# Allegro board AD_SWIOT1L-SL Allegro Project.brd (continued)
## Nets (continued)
AGND: C5.2(N2) C6.2(N2) C7.2(N2) C8.2(N2) C9.2(N2) C10.2(N2) C11.2(N2) C12.2(N2) C13.2(N2) C14.2(N2) C15.2(N2) C16.2(N2) C18.1 C19.1 C20.1 C21.2(N2) C22.2(N2) C23.2(N2) C24.2(N2) C25.1 C26.1 C27.1 C28.1 C29.1 C30.1 C31.1 C32.1 C33.2(N2) C34.2(N2) C35.2(N2) C36.2(N2) C37.2(N2) C38.2(N2) C39.2(N2) C40.2(N2) C41.2(N2) C42.1 C43.1 C44.1 C48.2(N2) C49.2(N2) C104.1 C105.1 C106.1 C110.1 C111.1 C112.1 C116.2(N2) C128.1 C129.1 C130.1 C136.1 C137.2(N2) C144.N(N2) C147.1 D1.2(N2) D2.2(N2) D3.2(N2) D4.2(N2) D17.1 P2.9(N9) P2.10 P4.1 P6.2 P6.4 P6.6 P6.8(N8) R28.2(N2) R47.2(N2) R50.2(N2) R51.2(N2) R52.2(N2) R53.2(N2) R54.2(N2) R56.2(N2) R70.2(N2) R76.2(N2) R78.2(N2) R80.2(N2) T1.8(SECDOT) TP1.1(N1) TP8.1(N1) TP10.1(N1) U2.8 U2.25 U2.28 U2.40 U2.41 U2.54 U2.PAD U3.1 U3.2 U3.14 U3.23 U3.30 U3.38 U3.47 U3.PAD U6.2 U6.10 U7.2 U7.10 U12.9 U12.10 U12.15 U12.16 U13.9 U13.10 U13.15 U13.16 U14.11 U14.12 U15.4 U15.9 U18.4 U25.4 U25.5 U25.16 U25.27 U25.PAD1
AVDD_H: C54.2(N2) C56.1 E1.2(N2) U8.16 U8.17
AVDD_L: C55.2(N2) C57.1 E2.2(N2) U8.22
AVSS: C20.2(N2) U2.27
DGND: C47.2(N2) C50.2(N2) C51.2(N2) C52.2(N2) C53.2(N2) C54.1 C55.1 C56.2(N2) C57.2(N2) C58.2(N2) C59.2(N2) C60.1 C61.1 C62.1 C63.1 C64.1 C65.1 C66.1 C67.1 C68.1 C69.1 C70.2(N2) C71.2(N2) C72.2(N2) C73.2(N2) C74.2(N2) C75.2(N2) C76.2(N2) C77.2(N2) C78.2(N2) C79.2(N2) C80.2(N2) C81.2(N2) C82.2(N2) C83.2(N2) C84.1 C85.2(N2) C86.2(N2) C87.2(N2) C88.1 C89.1 C90.1 C91.2(N2) C92.2(N2) C93.2(N2) C94.1 C95.1 C96.2(N2) C97.2(N2) C98.1 C99.2(N2) C100.2(N2) C101.2(N2) C102.2(N2) C103.2(N2) C107.2(N2) C108.1 C109.1 C115.N(N2) C117.2(N2) C118.2(N2) C119.1 C120.2(N2) C121.1 C122.2(N2) C123.2(N2) C124.2(N2) C125.2(N2) C126.2(N2) C127.2(N2) C131.1 C132.2(N2) C133.N(N2) C134.N(N2) C135.2(N2) C136.2(N2) C138.2(N2) C139.2(N2) C140.N(N2) C142.2(N2) C146.2(N2) D5.2(N2) D9.A(P) D19.2(N2) JP1.3 P1.3 P1.5 P1.9 Q12.1 Q12.3(S) Q13.2(S) Q20.2(S) Q21.2(S) R36.2(N2) R37.2(N2) R38.2(N2) R41.2(N2) R44.2(N2) R46.2(N2) R59.2(N2) R61.2(N2) R62.1 R126.2(N2) S1.2(B) T2.9 TP4.1(N1) TP6.1(N1) TP12.1(N1) TP14.1(N1) TP16.1(N1) U1.11 U1.27 U1.29 U1.47 U1.60 U1.80 U1.81 U1.85 U1.89(VSS_9) U1.98 U1.119 U1.136 U4.4 U4.5 U4.6 U4.7 U5.6 U5.PAD U6.11 U6.12 U7.11 U7.12 U8.PAD U9.B3 U9.C1 U9.E5(VSSQ_2) U10.B3 U10.C1 U10.E5(VSSQ_2) U11.4 U12.1 U12.2 U12.7 U12.8 U13.1 U13.2 U13.7 U13.8 U14.10 U16.2 U16.7 U16.10 U16.11 U16.PAD U17.3 U17.PAD U18.5 U19.5 U19.13 U25.3 U25.28 U25.33 U25.34 U25.PAD2 U25.PAD3 Y1.2 Y1.4
GND_EARTH: C113.2(N2) C143.2(N2) D6.3(E_3) P3.3(N3) R36.1 TP2.1(N1)
V5: C42.2(N2) U3.31
VCC_1: C131.2(N2) R64.1 U16.3
VDD_1: C34.1 Q6.1 Q6.2 Q6.3(S3) U3.17
VDD_2: C33.1 Q5.1 Q5.2 Q5.3(S3) U3.20
VDD_3: C35.1 Q7.1 Q7.2 Q7.3(S3) U3.41
VDD_4: C36.1 Q8.1 Q8.2 Q8.3(S3) U3.44
VDD_24V: C18.2(N2) C19.2(N2) C26.2(N2) C27.2(N2) R27.1 S2.6(NO2) U2.7 U2.42
VDD_24V_MAX14906: C32.2(N2) C41.1 C43.2(N2) Q5.5 Q5.6 Q5.7 Q5.8 Q6.5 Q6.6 Q6.7 Q6.8 Q7.5 Q7.6 Q7.7 Q7.8 Q8.5 Q8.6 Q8.7 Q8.8 R34.1 S2.5 U3.10(VLED_1) U3.11
VDDOK: DS9.C U3.3
VIN_SYS: C47.1 C138.1 C139.1 D11.A(P) D15.C D18.C JP1.1 R49.1 T1.1 U16.1(VIN) U25.30 U25.31
AD74413R_ADC_RDY: U1.75 U6.18
AD74413R_ADC_RDY_ISO: R84.2(N2) U2.52 U6.3
AD74413R_ALERT: U1.31 U25.38
AD74413R_ALERT_ISO: R79.2(N2) U2.53 U25.21
AD74413R_GPO_A: U1.45 U14.5
AD74413R_GPO_A_ISO: U2.19 U14.16
AD74413R_GPO_B: U1.46 U14.6
AD74413R_GPO_B_ISO: U2.20 U14.15
AD74413R_GPO_C: U1.48 U14.7
AD74413R_GPO_C_ISO: U2.21 U14.14
AD74413R_GPO_D: U1.49 U14.8
AD74413R_GPO_D_ISO: U2.22 U14.13
AD74413R_LDAC: U1.100 U25.37
AD74413R_LDAC_ISO: R78.1 U2.58 U25.22
AD74413R_RESET: U1.103 U25.36
AD74413R_RESET_ISO: R75.2(N2) U2.62 U25.23
ADIN1110_RESET: U1.121 U8.5
ADT75_OS__ALLERT: R94.2(N2) U1.39 U4.3
ALDO1V8: C22.1 C25.2(N2) U2.10
ALDO5V: C21.1 U2.9
CABLE+: C143.1 D6.1 L1.4(N4) P3.1 R73.1
CABLE-: C113.1 D6.2 L1.3 P3.2 R74.1
CASCODE_A: Q1.3 U2.64
CASCODE_B: Q2.3 U2.17
CASCODE_C: Q3.3 U2.32
CASCODE_D: Q4.3 U2.49
CCOMP_A: C1.1 U2.63
CCOMP_B: C4.1 U2.18
CCOMP_C: C2.1 U2.31
CCOMP_D: C3.1 U2.50
CH_1: C1.2(N2) C13.1 C40.1 D1.1 P6.1 R1.2(N2) R9.2(N2) R17.1 U3.15 U3.16
CH_2: C4.2(N2) C14.1 C39.1 D2.1 P6.3 R3.2(N2) R11.2(N2) R18.1 U3.21 U3.22
CH_3: C2.2(N2) C15.1 C38.1 D3.1 P6.5 R5.2(N2) R13.2(N2) R19.1 U3.39 U3.40
CH_4: C3.2(N2) C16.1 C37.1 D4.1 P6.7 R7.2(N2) R15.2(N2) R20.1 U3.45 U3.46
DATA_AND_POWER_N: C46.2(N2) L1.2 L2.2 R71.2(N2) R74.2(N2)
DATA_AND_POWER_P: C45.2(N2) L1.1 L2.3 R72.2(N2) R73.2(N2)
DATA_N: C46.1 D19.1 R23.2(N2) R24.2(N2) R71.1
DATA_P: C45.1 D5.1 R22.2(N2) R25.2(N2) R72.1
DLDO1V8: C23.1 C130.2(N2) U2.57
DLDO_1P1: C58.1 C60.2(N2) U8.23 U8.24
FIELD_POWER_DETECTED: U1.90 U18.6
FIELD_POWER_DETECTED_ISO: S2.2 U18.3
FLED: DS2.C DS4.C DS6.C DS8.C U3.4
G1: Q6.4 U3.18
G2: Q5.4 U3.19
G3: Q7.4 U3.42
G4: Q8.4 U3.43
GATE: Q9.4 R40.2(N2) U19.12
HYP_CLK: U1.65 U9.B2 U10.B2
HYP_CLKN: U1.64 U9.B1 U10.B1
HYP_CS0N: U1.52 U10.A3
HYP_CS1N: R82.2(N2) U1.44 U9.A3
HYP_D0: U1.53 U9.D3 U10.D3
HYP_D1: U1.58 U9.D2 U10.D2
HYP_D2: U1.62 U9.C4 U10.C4
HYP_D3: U1.66 U9.D4 U10.D4
HYP_D4: U1.56 U9.D5 U10.D5
HYP_D5: U1.59 U9.E3 U10.E3
HYP_D6: U1.63 U9.E2 U10.E2
HYP_D7: U1.67 U9.E1 U10.E1
HYP_RESET: U1.50 U9.A4 U10.A4
HYP_RWDS: U1.68 U9.C3 U10.C3
I2C1_SCL: R95.2(N2) U1.20 U4.2
I2C1_SDA: R96.2(N2) U1.19 U4.1
INT: U1.127 U8.25
L1: R33.2(N2) U3.8
L2: R32.2(N2) U3.7
L3: R31.2(N2) U3.6
L4: R30.2(N2) U3.5
LED1: Q20.1 U1.144
LED2: Q21.1 U1.143
LGATE1: Q12.2 U19.9
LGATE2: Q12.4 U19.8
LINK_ST: U1.130 U8.4
LTC9111_IN: C118.1 D7.C D8.C D9.C Q9.5 Q9.6 Q9.7 Q9.8 R42.1 U19.3
LX: L4.1 U16.12
MAX14906_D1: R129.2(N2) U1.97 U12.6
MAX14906_D1_ISO: R50.1 R132.2(N2) U3.13 U12.11
MAX14906_D2: R127.2(N2) U1.96 U12.5
MAX14906_D2_ISO: R52.1 R134.2(N2) U3.24 U12.12
MAX14906_D3: R130.2(N2) U1.95 U13.6
MAX14906_D3_ISO: R51.1 R133.2(N2) U3.37 U13.11
MAX14906_D4: R128.2(N2) U1.94 U13.5
MAX14906_D4_ISO: R53.1 R135.2(N2) U3.48 U13.12
MAX14906_EN: U1.72 U7.15
MAX14906_EN_ISO: U3.27 U7.6
MAX14906_FAULT: U1.71 U7.17
MAX14906_FAULT_ISO: R69.2(N2) U3.29 U7.4
MAX14906_READY: U1.70 U7.18
MAX14906_READY_ISO: R70.1 U3.26 U7.3
MAX14906_SYNCH: R37.1 U1.91 U7.16
MAX14906_SYNCH_ISO: U3.36 U7.5
MAXQ1065_PDWN: U1.3 U5.7
MAXQ1065_RDY: U1.1 U5.11
MAXQ1065_WDI: U1.2 U5.9(WDI)
PMOD_IRQ: U1.93 U18.7
PMOD_IRQ_ISO: P2.1 U18.2
POWER_N: C114.2(N2) D7.A(P) L2.4(N4) Q11.3 Q12.5 Q12.6 U19.2
POWER_P: D8.A(P) L2.1 Q10.3 Q12.7 Q12.8 R39.1 U19.1
PWRGD: Q13.1 R57.2(N2) U25.35
REFOUT: C106.2(N2) U2.29 U2.30
RSTN: C180.2(N2) P1.10(N5) R106.2(N2) R125.2(N2) S1.1 U1.114
RXN: R21.1 R23.1 U8.13
RXP: R25.1 R26.1 U8.14
SCCP: Q10.1 Q11.1 U19.7
SENSEH_A: R2.1 U2.1
SENSEH_B: R4.1 U2.16
SENSEH_C: R6.1 U2.33
SENSEH_D: R8.1 U2.48
SENSEHF_A: C6.1 R10.1 U2.2
SENSEHF_B: C8.1 R12.1 U2.15
SENSEHF_C: C10.1 R14.1 U2.34
SENSEHF_D: C12.1 R16.1 U2.47
SENSEL_A: R1.1 U2.3
SENSEL_B: R3.1 U2.14
SENSEL_C: R5.1 U2.35
SENSEL_D: R7.1 U2.46
SENSELF_A: C5.1 R9.1 U2.4
SENSELF_B: C7.1 R11.1 U2.13
SENSELF_C: C9.1 R13.1 U2.36
SENSELF_D: C11.1 R15.1 U2.45
SLED: DS1.C DS3.C DS5.C DS7.C U3.9
SLEW: JP1.2(COM) U25.32
SPI0_MISO: U1.138 U5.4
SPI0_MOSI: U1.141 U5.3
SPI0_SCK: U1.142 U5.2
SPI0_SS0: U1.10 U5.5
SPI1_MISO: U1.117 U6.17
SPI1_MISO_ISO: P2.6 U3.32 U6.4
SPI1_MOSI: U1.118 U6.15
SPI1_MOSI_ISO: P2.4 U3.35 U6.6
SPI1_SCK: U1.115 U6.14
SPI1_SCK_ISO: P2.8 U3.33 U6.7
SPI1_SS2: U1.92 U7.13
SPI1_SS2_ISO: P2.2 U7.8
SPI1_SS3: U1.116 U6.13
SPI1_SS3_ISO: U3.34 U6.8
SPI2_MISO__SPI_CFG1: U1.123 U8.2
SPI2_MOSI: U1.124 U8.1
SPI2_SCK: U1.122 U8.38
SPI2_SS0: U1.125 U8.29
SPI3_MISO: U1.35 U25.1
SPI3_MISO_ISO: R80.1 U2.51 U25.7
SPI3_MOSI: U1.36 U25.41
SPI3_MOSI_ISO: R76.1 U2.60 U25.8
SPI3_SCK: U1.30 U25.40
SPI3_SCK_ISO: R77.2(N2) U2.59 U25.9
SPI3_SS3: U1.32 U25.2
SPI3_SS3_ISO: U2.61 U25.6
SPI_CFG1: U1.120 U8.37
SPIXF_SCK: U1.13 U11.6
SPIXF_SDIO0: U1.17 U11.5
SPIXF_SDIO1: U1.15 U11.2
SPIXF_SDIO2: U1.22 U11.3(WP_N/SIO2)
SPIXF_SDIO3: U1.23 U11.7
SPIXF_SS0: U1.12 U11.1
SPOE_OUT: D15.A(P) R123.2(N2)
SPOE_OUT_O: C120.1 C122.1 Q9.1 Q9.2 Q9.3(S3) R66.1 R123.1 TP3.1(N1) U19.11
STBY: C135.1 U19.4(STBY) U19.10
SW: D14.A(P) R55.2(N2) R68.2(N2) T2.3 U15.5
SWP: D12.A(P) T1.4 U25.29
SWPD_EN: U1.133 U8.33
TC: R67.2(N2) U15.8
TCK: P1.4 U1.110
TMS: P1.2 U1.113
TS_CAPT: U1.129 U8.40
TS_TIMER__MS_SEL: U1.131 U8.30
TX2P4_EN: U1.134 U8.31
TXN: R24.1 R26.2(N2) U8.12
TXP: R21.2(N2) R22.1 U8.15
UART0_RX: P1.8 U1.132
UART0_TX: P1.6 U1.137
UNNAMED_2_ADMAXQ1065_I121_CEXT: C100.1 U5.1
UNNAMED_2_ADMAXQ1065_I121_RESETOUT: R106.1 U5.10
UNNAMED_2_CAP_I138_N1: C180.1 R126.1
UNNAMED_2_DIOLED_I129_N: DS17.C Q20.3
UNNAMED_2_DIOLED_I129_P: DS17.A(P) R116.2(N2)
UNNAMED_2_DIOLED_I131_N: DS18.C Q21.3
UNNAMED_2_DIOLED_I131_P: DS18.A(P) R117.2(N2)
UNNAMED_6_ADIN1110V2_I1_CEXT2: C52.1 U8.19
UNNAMED_6_ADIN1110V2_I1_CEXT3: C53.1 U8.20
UNNAMED_6_ADIN1110V2_I1_LED0: R102.2(N2) U8.3
UNNAMED_6_ADIN1110V2_I1_LED1: R104.2(N2) R105.2(N2) U8.6
UNNAMED_6_ADIN1110V2_I1_TEST1: R35.1 U8.26
UNNAMED_6_CAP_I79_N2: C119.2(N2) R40.1
UNNAMED_6_CAP_I114_N1: C114.1 R39.2(N2)
UNNAMED_6_CAP_I146_N1: C117.1 R42.2(N2)
UNNAMED_6_CAPP_I143_N1: C115.P C133.P R66.2(N2)
UNNAMED_6_DIOLED_I64_N: DS10.C R102.1
UNNAMED_6_DIOLED_I147_N: DS11.C R105.1
UNNAMED_6_RES_I107_N1: Q11.2(S) R41.1
UNNAMED_6_RES_I109_N1: Q10.2(S) R38.1
UNNAMED_7_ADLT8304_I142_EN: R28.1 R29.1 U15.1
UNNAMED_7_ADLT8304_I142_RFB: R55.1 U15.6
UNNAMED_7_ADLT8304_I142_RREF: R54.1 R67.1 U15.7
UNNAMED_7_ADMAX17761_I143_EN: R49.2(N2) R59.1 U16.4
UNNAMED_7_ADMAX17761_I143_FB: R60.2(N2) R61.1 R63.1 U16.8
UNNAMED_7_ADMAX17761_I143_RESETN: R64.2(N2) U16.5
UNNAMED_7_ADMAX17761_I143_RT: R62.2(N2) U16.6
UNNAMED_7_ADMAX17761_I143_SS: C127.1 U16.9
UNNAMED_7_ADP22X_I83_ADJ1: R43.2(N2) R44.1 U17.8
UNNAMED_7_ADP22X_I83_ADJ2: R45.2(N2) R46.1 U17.4
UNNAMED_7_ADP1032_I2_SW2: L3.1 U25.17
UNNAMED_7_ADP1032_I2_SYNC: R56.1 U25.14
UNNAMED_7_CAP_I60_N1: C126.1 R63.2(N2)
UNNAMED_7_CAP_I103_N1: C137.1 U15.2
UNNAMED_7_CAP_I154_N2: C141.2(N2) R68.1
UNNAMED_7_CAP_I167_N1: C145.1 R83.2(N2)
UNNAMED_7_DIO_I14_P: D10.A(P) T1.5
UNNAMED_7_DIOLED_I159_N: DS12.C Q13.3
UNNAMED_7_DIOLED_I159_P: DS12.A(P) R81.2(N2)
UNNAMED_7_DIOSCHOTTKY_I9_N: D11.C D12.C
UNNAMED_7_DIOSCHOTTKY_I132_P: D16.A(P) R83.1 T2.7
UNNAMED_7_DIOSCHOTTKY_I135_N: D13.C D14.C
UNNAMED_7_RES_I152_N1: R47.1 S2.3
UNNAMED_7_RES_I153_N1: R58.1 S2.1
UNNAMED_8_DIOLED_I6_P: DS9.A(P) R34.2(N2)
UNNAMED_8_DIOLED_I35_P: DS7.A(P) DS8.A(P) R33.1
UNNAMED_8_DIOLED_I37_P: DS5.A(P) DS6.A(P) R32.1
UNNAMED_8_DIOLED_I39_P: DS3.A(P) DS4.A(P) R31.1
UNNAMED_8_DIOLED_I41_P: DS1.A(P) DS2.A(P) R30.1
UNNAMED_9_AD74413_I30_CPUMPN: C17.2(N2) U2.26
UNNAMED_9_AD74413_I30_CPUMPP: C17.1 U2.24
UNNAMED_9_DIOBAV99LT1_I116_C: CR1.3 R2.2(N2) R10.2(N2) R17.2(N2)
UNNAMED_9_DIOBAV99LT1_I116_P: CR1.1(P) Q1.1 Q1.2 Q1.5 Q1.6
UNNAMED_9_DIOBAV99LT1_I117_C: CR2.3 R4.2(N2) R12.2(N2) R18.2(N2)
UNNAMED_9_DIOBAV99LT1_I117_P: CR2.1(P) Q2.1 Q2.2 Q2.5 Q2.6
UNNAMED_9_DIOBAV99LT1_I118_C: CR3.3 R6.2(N2) R14.2(N2) R19.2(N2)
UNNAMED_9_DIOBAV99LT1_I118_P: CR3.1(P) Q3.1 Q3.2 Q3.5 Q3.6
UNNAMED_9_DIOBAV99LT1_I119_C: CR4.3 R8.2(N2) R16.2(N2) R20.2(N2)
UNNAMED_9_DIOBAV99LT1_I119_P: CR4.1(P) Q4.1 Q4.2 Q4.5 Q4.6
VIOUTN_A: CR1.2 U2.6
VIOUTN_B: CR2.2 U2.11
VIOUTN_C: CR3.2 U2.38
VIOUTN_D: CR4.2 U2.43
VIOUTP_A: Q1.4(S) U2.5
VIOUTP_B: Q2.4(S) U2.12
VIOUTP_C: Q3.4(S) U2.37
VIOUTP_D: Q4.4(S) U2.44(VIOUTP_D)
VOUT1: C24.1 C48.1 D10.C R27.2(N2) TP7.1(N1) U25.18
VOUT2: C49.1 L3.2(N2) R48.2(N2) TP9.1(N1) U25.15(VOUT2)
XTAL_I: C50.1 U8.8 Y1.1
XTAL_O: C51.1 U8.9(XTAL_O) Y1.3(N2)

Pads without a net: P1 7; P2 3 5 7; T1 2 3 6 7; T2 1 2 4 6 8 10; U1 4 6 7 8 16 24 25 26 28 34 37 38 40 41 42 43 51 57 61 69 73 74 77 78 79 82 83 84 86 87 101 102 104 105 106 107 108 109 112 135 139 140; U2 39; U3 28; U5 8; U6 5 9 16 19; U7 7 9 14 19; U8 7 10 11 18 21 27 28 32 34 36 39; U9 A2 A5 B5 C2 C5; U10 A2 A5 B5 C2 C5; U12 4 13; U13 4 13; U14 2 3 4 9 17 18 19; U19 6; U25 11 12 13 19 24 25 26

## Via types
v1: diameter 0.508, hole 0.254, TOP to BOTTOM, 1639 vias
v2: diameter 0.457, hole 0.254, TOP to BOTTOM, 51 vias

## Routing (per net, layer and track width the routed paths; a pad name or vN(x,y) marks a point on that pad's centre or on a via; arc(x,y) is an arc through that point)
1V1: length 60.9
  TOP w0.254: 47.45,102.83 U1.5 ; U1.88 39.45,79.18 ; 42.95,102.83 U1.14
  TOP w0.457: v1(43.83,103.22) 43.37,103.68 C78.1 42.95,102.83 ; v1(48.19,103.68) C79.1 47.45,102.83
  TOP w0.483: 39.45,79.18 v1(39.45,78.6)
  TOP w0.508: 57.97,105.01 61.53,105.01 TP15.1 ; v1(39.45,78.6) 38.9,78.6 38.87,78.57 C80.1
  BOTTOM w0.508: v1(39.45,78.6) 39.45,79.88
  BOTTOM w0.635: v1(48.19,103.68) 50.12,103.68 50.93,102.87 50.93,102.87 52.62,101.18 56.12,101.18 56.76,101.81 56.76,104.35 v1(57.24,104.83) v1(57.97,104.83) v1(58.68,104.83) ; v1(48.19,103.68) 48.19,102.67 40.91,95.39 40.91,81.34 39.45,79.88 ; v1(48.19,103.68) 44.29,103.68 v1(43.83,103.22)
1V8: length 105.5
  TOP w0.254: U1.126 52.47,90.69 ; U9.B4 7.85,91.1 7.85,92.02 9,93.17 R82.1 ; U1.111 52.47,83.19 ; U1.33 33.45,102.7 ; U10.D1 16.18,88.04 16.17,88.04 ; C68.2 28.17,90.69 U1.55 ; U9.D1 4.76,88.04 ; U1.21 39.45,102.68 ; 44.95,78.98 U1.99
  TOP w0.288: U10.E4 19.26,88.12 19.26,90.12 U10.B4 ; U9.B4 7.84,90.12 7.84,88.12 U9.E4
  TOP w0.483: v1(38.65,102.9) C62.2 C66.2 39.45,102.68 ; 4.76,88.04 C91.1 ; C89.2 20.96,86.42 U10.E4 ; 44.95,78.98 45.15,78.78 C82.1 C83.1 v1(45.15,76.82) ; U11.8 C96.1 29.23,103.84 v1(30.18,102.89) ; C85.1 16.17,88.04 ; 33.45,102.7 C67.2 C63.2 v1(32.65,102.89) ; v1(73.01,104.76) C101.1 P1.1 ; v1(52.75,89.89) C65.2 C69.2 52.47,90.69 ; v1(52.77,82.18) 53.18,82.59 C142.1 52.47,83.19 ; U9.E4 9.54,86.42 C94.2 ; C68.2 C64.2 26.47,90.37 v1(26.3,90.2)
  TOP w0.635: v1(22.6,80.68) C87.1 C88.2 C89.2 ; v1(5.81,81.85) 3.51,84.14 C90.2 C92.1 C91.1 ; C85.1 C86.1 C84.2 v1(14.92,81.14) ; v1(11.17,81.14) C93.1 C95.2 C94.2
  L2_PWR w0.457: TP13.1 9.51,81.43 ; TP13.1 10.44,80.5 ; TP13.1 8.59,80.5 ; TP13.1 9.51,79.57
  L2_PWR w0.508: v1(26.3,90.2) 27.4,91.3 27.4,99.09
  BOTTOM w0.254: v1(73.01,104.76) 69.48,101.23 61.31,101.23 59.79,99.71 v1(58.13,99.71)
  vias: v1(57.42,100.42) v1(57.42,99.71) v1(58.13,100.42)
3V3: length 69.7
  TOP w0.178: 57.32,87.6 U8.35 ; 45.45,102.7 U1.9
  TOP w0.254: U1.54 28.17,91.19 C70.1 ; U1.18 40.95,102.7 ; U1.128 52.47,91.69 ; U1.76 33.45,79.18
  TOP w0.279: 63.88,99.67 U5.12 ; U17.1 U17.2 v1(53.51,102.74)
  TOP w0.305: U25.39 57.73,59.92 57.39,60.26 ; U4.8 C97.1
  TOP w0.33: U7.20 16.1,75.83 ; U6.20 8.14,75.83 ; 51.25,75.83 U14.1
  TOP w0.457: 57.39,60.26 57.23,60.42 C121.2 56.9,61.26 56.4,61.76 v1(56.4,62.14)
  TOP w0.483: 8.14,75.83 C102.1 v1(8.14,77.07) ; R104.1 DS11.A v1(62.66,79.26) ; C70.1 C75.1 26.54,91.51 26.34,91.71 v1(26.32,91.71) ; 57.32,87.6 C59.1 C61.2 v1(56.2,89.14) ; R127.1 v1(40.21,75.93) C108.2 U12.3 ; v1(63.88,102.21) C98.2 C99.1 63.88,99.67 ; v1(41.75,102.97) C76.1 C72.1 40.95,102.7 ; v1(16.1,77.07) C103.1 16.1,75.83 ; R128.1 v1(29.54,75.93) C109.2 U13.3 ; E1.1 v1(69.66,88.78) ; R117.1 v1(74.24,99.37) ; E2.1 v1(64.61,93.48) ; R116.1 74.87,104.38 v1(74.23,104.38) ; 45.45,102.7 C73.1 C77.1 46.24,103.67 v1(46.24,102.9) ; v1(51.25,77.32) C107.1 51.25,75.83 ; R130.1 v1(24.83,75.93) ; R35.2 v1(59.2,92.8) ; 52.47,91.69 C71.1 C74.1 v1(52.75,92.49) ; v1(8.63,100.26) C97.1 ; C81.1 v1(33.45,78.65) 33.45,79.18 ; R125.1 v1(54.08,85.42) ; v1(17.31,103.44) R94.1 R95.1 R96.1 ; R57.1 v1(60.19,63.74) ; R129.1 v1(35.51,75.93) ; v1(58.2,78.93) DS10.A ; v1(61.2,66.1) R81.1
  TOP w0.508: U18.8 C146.1 v1(2.99,75.4)
  L2_PWR w0.508: v1(26.32,91.71) 26.32,99.11
  vias: v1(57.98,102.24) v1(58.31,74.64) v1(58.31,73.93) v1(58.31,73.22) v1(59.01,74.64) v1(59.01,73.93) v1(59.01,73.22) v1(60.47,102.75) v1(60.47,102.05) v1(61.18,102.75) v1(61.18,102.05)
3V3_ISO: length 112.4
  TOP w0.254: U25.10 57.73,50.66 57.62,50.55 ; U6.1 C104.2 ; U7.1 C105.2
  TOP w0.279: v1(32.09,51.64) 31.81,51.64 31.33,52.12 U3.12
  TOP w0.305: 29.75,40.69 29.37,40.31 U2.23 ; U2.55 27.87,29.52 28.11,29.27 28.37,29.52 U2.56 ; 31.63,60.4 31.33,60.1 U3.25 ; U25.20 62.73,50.96
  TOP w0.33: U14.20 51.25,66.51
  TOP w0.457: 62.73,50.96 63.74,49.95 C128.2 v1(63.74,49.18) ; R79.1 v1(55.9,42.86) ; v1(53.98,47.41) R75.1 53.98,48.97 R77.1 ; v1(56.73,49.44) C129.2 57.25,50.18 57.62,50.55 ; R58.2 v1(54.75,30.88)
  TOP w0.483: 29.75,40.69 29.94,40.88 C29.2 29.94,42.52 29.46,43.01 C28.2
  TOP w0.508: 31.63,60.4 31.73,60.51 C44.2 v1(31.73,61.95) v1(31.73,62.69) ; v1(30.24,65.65) C111.2 U13.14 ; v1(51.25,65) C112.2 51.25,66.51 ; v1(2.99,66.92) C147.2 U18.1 ; v1(28.11,25.69) C31.2 C30.2 28.11,29.27 ; R132.1 v1(35.5,65.25) ; R134.1 v1(39.97,65.25) ; R135.1 v1(29.3,65.25) ; C105.2 v1(16.1,65.25) ; v1(40.91,65.65) C110.2 U12.14 ; v1(8.14,65.25) C104.2 8.91,65.99 R84.1 ; v1(19.45,64.25) R69.1 ; R133.1 v1(24.83,65.25)
  L2_PWR w0.457: 6.91,49.71 P2.11 ; P2.11 8.02,50.83 ; P2.11 9.14,49.71 ; P2.11 8.02,48.6 ; P2.12 6.6,49.71 ; P2.12 5.48,50.83 ; P2.12 4.37,49.71 ; P2.12 5.48,48.6
  BOTTOM w0.457: v1(55.9,42.86) 55.9,41.83 54.75,40.67 v1(54.75,30.88)
  BOTTOM w0.508: 32.08,51.64 31.49,51.64 31.49,51.65 ; 32.08,51.64 v1(32.09,51.64) 31.49,51.04 ; 32.08,51.64 31.49,52.23
  BOTTOM w0.762: v1(31.73,62.69) v1(31.73,61.95) 31.49,61.71 31.49,45.73 v1(29.58,43.82) ; 28.67,43.82 29.58,42.91 ; 28.67,43.82 v1(28.66,43.82) ; 28.67,43.82 v1(29.58,43.82) ; 29.58,42.91 v1(29.58,43.82) ; 29.58,42.91 29.58,41.49 32.96,38.11 32.96,31.38 28.11,26.53 v1(28.11,25.69)
  vias: v1(61.11,43.75) v1(61.11,43.04) v1(61.82,43.75) v1(61.82,43.04)
3V3_O: length 12.4
  TOP w0.457: 58.18,68.42 TP11.1 ; TP11.1 58.18,70.28 ; TP11.1 57.25,69.35 ; TP11.1 59.11,69.35
  TOP w0.508: v1(63.64,78.28) R60.1
  L2_PWR w0.508: v1(65.27,70.98) 65.27,76.66 v1(63.64,78.28)
24V_EXT: length 36.4
  TOP w0.457: R29.2 59.4,13.48 ; R29.2 60.13,12.88 ; R29.2 58.66,12.88
  TOP w0.762: S2.4 61.94,29.98 ; S2.4 63.39,31.43 ; S2.4 63.39,28.54 ; S2.4 64.84,29.98 ; C144.P 59.65,24.22 ; C144.P 63.38,24.22 ; C144.P 61.51,25.31 ; C144.P 61.51,23.12 ; D17.2 50,20.19 ; D17.2 52.8,20.19 ; D17.2 51.4,21.73 ; D17.2 51.4,18.65 ; P4.2 56.54,13.49 ; P4.2 53.79,13.49 ; P4.2 55.16,12.12 ; P4.2 55.16,14.87
  L2_PWR w0.762: P4.2 55.16,14.87 ; P4.2 55.16,12.12 ; P4.2 56.54,13.49 ; P4.2 53.79,13.49
  L2_PWR w0.889: S2.4 64.82,29.98 ; S2.4 63.39,28.55 ; S2.4 63.39,31.42 ; S2.4 61.95,29.98
  vias: v1(54.65,20.41) v1(54.65,19.14) v1(54.65,17.87) v1(54.65,16.6) v1(55.92,20.41) v1(55.92,19.14) v1(55.92,17.87) v1(55.92,16.6) v1(57.19,20.41) v1(57.19,19.14) v1(57.19,17.87) v1(57.19,16.6) v1(63.87,6.06) v1(63.87,5.35) v1(64.59,6.06) v1(64.59,5.35) v1(65.6,29.98) v1(65.6,28.71) v1(65.6,27.44) v1(65.6,26.17) v1(65.6,24.9) v1(66.87,29.98) v1(66.87,28.71) v1(66.87,27.44) v1(66.87,26.17) v1(66.87,24.9) v1(68.14,29.98) v1(68.14,28.71) v1(68.14,27.44) v1(68.14,26.17) v1(68.14,24.9) v1(69.41,29.98) v1(69.41,28.71) v1(69.41,27.44) v1(69.41,26.17) v1(69.41,24.9)
36V: length 3.7
  TOP w0.508: TP5.1 89.74,26.94 ; TP5.1 88.81,27.87 ; TP5.1 87.89,26.94 ; TP5.1 88.81,26.01
AGND: length 194.8
  TOP w0.254: U14.12 v1(46.05,66.31) ; U14.11 v1(45.4,66.02) ; U7.10 v1(21.95,66.31) ; U6.10 v1(13.99,66.31)
  TOP w0.457: U7.2 16.75,68.84 ; C20.1 v1(26.74,44.88) ; C20.1 v1(26.74,46.73) ; C20.1 v1(25.43,45.81) ; C20.1 27.88,45.81 ; C137.2 R28.2 ; C137.2 60.16,7.55 ; C137.2 58.63,7.55 ; C137.2 59.4,6.41 ; 18.92,36.69 C9.2 19.45,36.12 ; 64.64,49.34 C128.1 ; C128.1 64.64,50.48 ; C128.1 65.18,49.91 ; 26.09,42.06 C106.1 v1(26.09,40.73) ; 55.83,49.61 C129.1 55.3,50.18 ; 70.58,37.87 TP8.1 ; TP8.1 69.65,38.79 ; TP8.1 70.58,39.72 ; TP8.1 71.5,38.79 ; C5.2 38.31,32.24 ; P2.10 5.48,53.37 ; P2.10 4.37,52.25 ; P2.10 5.48,51.14 ; P2.10 6.6,52.25 ; 50.35,66.31 C112.1 49.81,65.73 ; 52.44,50.26 R76.2 52.44,51.41 ; 18.92,32.47 C11.2 ; 6.06,69.78 U18.4 6.67,68.57 ; C42.1 30.38,63.34 ; C42.1 29.52,64.36 ; C42.1 29.52,62.33 ; 52.44,52.17 R80.2 52.44,53.31 ; C8.2 38.31,38.88 ; 39.39,34.36 C25.1 39.96,34.89 ; 36.98,34.31 C21.2 38.13,34.31 ; P2.9 8.02,53.37 ; P2.9 9.14,52.25 ; P2.9 8.02,51.14 ; P2.9 6.91,52.25 ; 20.25,34.32 TP1.1 ; TP1.1 21.99,35.06 ; TP1.1 21.74,34.32 ; TP1.1 20.25,35.81 ; 59.49,41.42 R47.2 ; R47.2 60.02,42 ; R47.2 59.49,42.57 ; R28.2 59.97,9.23 ; R28.2 58.83,9.23 ; 52.43,44.61 TP10.1 ; TP10.1 54.28,44.61 ; TP10.1 53.36,43.68 ; TP10.1 53.36,45.54 ; 53.57,46.27 R78.2 54.1,45.7 ; 33.17,61.22 C44.1 32.63,60.65 ; 18.92,30.06 C12.2 ; 61.67,18.56 R54.2 61.13,17.99 ; 1.68,66.02 C147.1 2.25,65.49 ; 22.18,34.72 C27.1 23.32,34.72 ; C6.2 38.31,29.83 ; 58.39,50.36 R56.2 ; 38.55,34.36 C22.2 ; U6.2 8.79,68.84 ; C19.1 38.31,33.54 ; 18.92,39.11 C10.2 ; C7.2 38.31,36.47
  TOP w0.483: C41.2 v1(32.78,50.9) ; C29.1 30.84,42.44
  TOP w0.508: U13.10 v1(25.16,67.2) ; C110.1 v1(41.81,65.65) ; C23.2 C130.1 v1(29.77,25.69) ; C147.1 v1(2.99,66.02) ; R50.2 v1(35.5,66.39) ; R52.2 v1(39.97,66.39) ; U13.9 v1(23.89,67.2) ; C105.1 v1(15.2,65.25) ; U12.10 v1(35.83,67.2) ; U18.4 v1(6.06,67.2) ; R53.2 v1(29.3,66.39) ; R70.2 v1(17.74,64.25) ; C112.1 v1(50.35,65) ; C104.1 v1(7.24,65.25) ; 27.4,27.97 27.21,27.79 C30.1 C31.1 v1(27.21,25.69) ; U12.15 v1(42.18,67.2) ; C111.1 v1(31.14,65.65) ; U13.15 v1(31.51,67.2) ; U12.16 v1(43.45,67.2) ; C44.1 v1(32.63,61.95) ; R51.2 v1(24.83,66.39) ; U12.9 v1(34.56,67.2) ; U13.16 v1(32.78,67.2)
  TOP w0.635: P6.8 15.28,8.11 ; P6.8 16.53,6.87 ; P6.8 15.28,5.62 ; P6.8 14.04,6.87 ; P6.2 39.39,6.87 ; P6.2 38.14,8.11 ; P6.2 38.14,5.62 ; P6.2 36.9,6.87 ; 21.66,6.87 P6.6 ; P6.6 22.9,5.62 ; P6.6 24.15,6.87 ; P6.6 22.9,8.11 ; 29.28,6.87 P6.4 ; P6.4 30.52,5.62 ; P6.4 31.77,6.87 ; P6.4 30.52,8.11
  TOP w0.762: 48.79,13.49 P4.1 ; P4.1 50.16,14.87 ; P4.1 50.16,12.12 ; P4.1 51.54,13.49 ; D17.1 v1(51.4,23.17) ; D17.1 v1(52.97,24.89) ; D17.1 v1(49.82,24.89) ; D17.1 v1(51.4,26.6) ; C144.N 53.85,24.22 ; C144.N 55.71,23.12 ; C144.N 55.71,25.31 ; C144.N 57.58,24.22
  L3_GND w0.457: TP10.1 53.36,45.54 ; TP10.1 53.36,43.68 ; TP10.1 54.28,44.61 ; TP10.1 52.43,44.61 ; P2.10 5.48,53.37 ; P2.10 5.48,51.14 ; P2.10 6.6,52.25 ; P2.10 4.37,52.25 ; TP8.1 71.5,38.79 ; TP8.1 70.58,39.72 ; TP8.1 70.58,37.87 ; TP8.1 69.65,38.79 ; 8.02,51.14 P2.9 ; P2.9 8.02,53.37 ; P2.9 6.91,52.25 ; P2.9 9.14,52.25
  L3_GND w0.508: TP1.1 20.25,34.32 ; TP1.1 21.1,35.06 21.76,35.72 ; TP1.1 20.25,35.81 ; TP1.1 21.74,34.32
  L3_GND w0.635: 22.9,5.62 P6.6 ; P6.6 24.15,6.87 ; P6.6 21.66,6.87 ; P6.6 22.9,8.11 ; P6.4 30.52,8.11 ; P6.4 31.77,6.87 ; P6.4 29.28,6.87 ; P6.4 30.52,5.62 ; P6.2 39.39,6.87 ; P6.2 38.14,5.62 ; P6.2 38.14,8.11 ; P6.2 36.9,6.87 ; P6.8 15.28,8.11 ; P6.8 15.28,5.62 ; P6.8 16.53,6.87 ; P6.8 14.04,6.87
  L3_GND w0.762: P4.1 50.16,14.87 ; P4.1 48.79,13.49 ; P4.1 50.16,12.12 ; P4.1 51.54,13.49
  BOTTOM w0.457: 70.58,37.87 TP8.1 ; TP8.1 71.5,38.79 ; TP8.1 69.65,38.79 ; TP8.1 70.58,39.72 ; P2.9 8.02,53.37 ; P2.9 9.14,52.25 ; P2.9 8.02,51.14 ; P2.9 6.91,52.25 ; 4.37,52.25 P2.10 ; P2.10 5.48,51.14 ; P2.10 5.48,53.37 ; P2.10 6.6,52.25
  BOTTOM w0.762: 48.79,13.49 P4.1 ; P4.1 50.16,14.87 ; P4.1 50.16,12.12 ; P4.1 51.54,13.49
  vias: v1(1.29,64.73) v1(1.29,60.92) v1(1.29,57.11) v1(1.29,53.3) v1(1.29,49.49) v1(1.29,45.68) v1(1.29,41.87) v1(1.29,38.06) v1(1.29,34.25) v1(1.29,30.44) v1(1.29,26.63) v1(1.29,22.82) v1(1.29,19.01) v1(1.29,15.2) v1(1.29,11.39) v1(1.29,7.58) v1(1.29,3.77) v1(1.41,69.96) v1(2.53,28.61) v1(3.27,42.93) v1(3.42,38.08) v1(3.42,34.25) v1(3.42,30.44) v1(3.52,62.11) v1(3.52,57.03) v1(3.52,51.95) v1(3.52,46.87) v1(3.52,6.23) v1(4.79,8.77) v1(4.79,3.69) v1(5.93,1.63) v1(6.06,69.96) v1(6.06,6.23) v1(6.62,63.38) v1(6.82,48.55) v1(6.92,37.25) v1(6.92,32.17) v1(6.95,42.33) v1(6.95,29.12) v1(7.33,8.77) v1(7.33,3.69) v1(8.37,69.99) v1(8.4,39.35) v1(8.49,27.95) v1(8.6,26.55) v1(8.6,21.47) v1(8.6,16.39) v1(8.6,11.31) v1(8.6,6.23) v1(8.68,34.96) v1(8.78,68.87) v1(9.29,45.2) v1(9.36,48.55) v1(9.74,1.63) v1(9.92,52.97) v1(9.87,8.77) v1(9.87,3.69) v1(11.19,55.51) v1(11.19,50.43) v1(11.14,11.31) v1(11.14,6.23) v1(11.7,69.99) v1(12.41,8.77) v1(12.41,3.69) v1(12.46,58.05) v1(12.46,52.97) v1(12.87,24.57) v1(12.87,20.76) v1(12.94,39.81) v1(12.94,36) v1(12.94,32.19) v1(12.94,28.38) v1(13.55,1.63) v1(13.76,60.21) v1(13.73,55.51) v1(13.96,43.6) v1(14.95,3.69) v1(15.05,69.99) v1(15.53,34.63) v1(15.53,33.71) v1(15.56,31.71) v1(15.56,27.11) v1(15.56,24.27) v1(15.64,37.4) v1(16.3,60.21) v1(16.47,35.49) v1(16.47,32.85) v1(16.65,46.29) v1(16.75,68.87) v1(16.91,37.4) v1(17.36,1.63) v1(17.49,3.69) v1(18.07,51.37) v1(18.43,69.99) v1(18.51,41.13) v1(18.56,30.06) v1(18.76,39.1) v1(18.76,36.69) v1(18.75,32.47) v1(18.84,52.08) v1(18.96,60.33) v1(19.52,23.28) v1(20.03,3.69) v1(20.08,61.65) v1(20.54,46.29) v1(21.22,50.89) v1(21.17,1.63) v1(21.25,60.31) v1(21.81,61.65) v1(21.94,69.96) v1(21.99,34.48) v1(22.11,41.08) v1(22.14,60.31) v1(22.19,51.67) v1(22.34,20.84) v1(22.57,3.69) v1(22.9,46.29) v1(23.41,39.63) v1(23.48,34.48) v1(23.87,69.96) v1(24.27,58.3) v1(24.6,27.64) v1(24.93,51.7) v1(24.93,50.89) v1(24.98,1.63) v1(25.11,3.69) v1(25.16,69.96) v1(25.21,23.28) v1(25.39,42.25) v1(25.58,37.53) v1(25.58,36.51) v1(25.58,35.5) v1(25.58,34.48) v1(25.58,33.47) v1(25.58,32.45) v1(25.58,31.43) v1(26.55,57.96) v1(26.55,56.94) v1(26.55,55.93) v1(26.55,54.91) v1(26.55,53.89) v1(26.6,37.53) v1(26.6,36.51) v1(26.6,35.5) v1(26.6,34.48) v1(26.6,33.47) v1(26.6,32.45) v1(26.6,31.43) v1(27.07,69.96) v1(27.4,29.09) v1(27.57,57.96) v1(27.57,56.94) v1(27.57,55.93) v1(27.57,54.91) v1(27.57,53.89) v1(27.61,37.53) v1(27.61,36.51) v1(27.61,35.5) v1(27.61,34.48) v1(27.61,33.47) v1(27.61,32.45) v1(27.61,31.43) v1(27.65,3.69) v1(28.39,20.84) v1(28.58,57.96) v1(28.58,56.94) v1(28.58,55.93) v1(28.58,54.91) v1(28.58,53.89) v1(28.63,37.53) v1(28.63,36.51) v1(28.63,35.5) v1(28.63,34.48) v1(28.63,33.47) v1(28.63,32.45) v1(28.63,31.43) v1(28.67,46.64) v1(28.79,1.63) v1(28.87,61.71) v1(28.84,24.16) v1(29.12,49.18) v1(29.12,47.56) v1(29.53,64.52) v1(29.6,57.96) v1(29.6,56.94) v1(29.6,55.93) v1(29.6,54.91) v1(29.6,53.89) v1(29.58,46.64) v1(29.65,37.53) v1(29.65,36.51) v1(29.65,35.5) v1(29.65,34.48) v1(29.65,33.47) v1(29.65,32.45) v1(29.65,31.43) v1(30.19,3.69) v1(30.5,46.64) v1(30.44,22.31) v1(30.61,57.96) v1(30.61,56.94) v1(30.61,55.93) v1(30.61,54.91) v1(30.61,53.89) v1(30.66,37.53) v1(30.66,36.51) v1(30.66,35.5) v1(30.66,34.48) v1(30.66,33.47) v1(30.66,32.45) v1(30.66,31.43) v1(30.85,42.6) v1(31.16,63.81) v1(31.51,69.96) v1(31.68,37.53) v1(31.68,36.51) v1(31.68,35.5) v1(31.68,34.48) v1(31.68,33.47) v1(31.68,32.45) v1(31.68,31.43) v1(32.45,60.49) v1(32.63,47.99) v1(32.63,46.16) v1(32.6,1.63) v1(32.73,3.69) v1(32.78,69.96) v1(32.88,58.3) v1(32.93,24.65) v1(33.31,59.65) v1(33.67,69.35) v1(33.85,29.19) v1(34.56,69.96) v1(34.81,27.95) v1(35.04,60.11) v1(35.07,51.85) v1(35.19,44.87) v1(35.27,3.69) v1(35.83,69.96) v1(35.91,60.36) v1(35.85,51.04) v1(36.01,47.53) v1(36.41,1.63) v1(36.74,50.22) v1(36.82,34.32) v1(37.05,61.35) v1(37.81,3.69) v1(38.09,44.87) v1(38.24,60.36) v1(38.32,34.17) v1(38.5,36.51) v1(38.47,33.54) v1(38.5,32.24) v1(38.48,29.83) v1(38.57,52.08) v1(38.67,38.87) v1(38.7,27.77) v1(38.85,61.45) v1(39,69.96) v1(39.21,51.47) v1(39.51,47.46) v1(39.92,43.95) v1(39.92,24.75) v1(40.12,63.99) v1(40.12,34.91) v1(40.22,1.63) v1(40.35,3.69) v1(41.32,27.42) v1(41.29,24.75) v1(41.39,61.45) v1(41.39,56.37) v1(41.47,33.36) v1(41.47,32.44) v1(41.93,49.08) v1(42.18,69.96) v1(42.66,63.99) v1(42.89,18.93) v1(42.89,3.69) v1(43.07,43.87) v1(43.47,69.96) v1(43.7,39.84) v1(43.7,36.03) v1(43.7,32.22) v1(43.7,28.41) v1(43.93,61.45) v1(43.93,56.37) v1(43.93,51.29) v1(44.03,1.63) v1(44.16,16.39) v1(44.69,46.39) v1(45.2,63.99) v1(45.2,58.91) v1(45.2,53.83) v1(45.43,18.93) v1(45.43,13.85) v1(45.43,8.77) v1(45.43,3.69) v1(45.71,69.53) v1(46.27,35.72) v1(46.27,33.71) v1(46.27,31.73) v1(46.57,21.57) v1(46.7,16.39) v1(46.7,11.31) v1(46.7,6.23) v1(47.84,1.63) v1(47.97,18.93) v1(47.97,13.85) v1(47.97,8.77) v1(47.97,3.69) v1(48.3,69.55) v1(48.5,23.5) v1(49.24,52.76) v1(49.24,16.39) v1(49.24,11.31) v1(49.24,6.23) v1(50.51,8.77) v1(50.51,3.69) v1(50.66,69.53) v1(50.82,51.24) v1(51.55,63.13) v1(51.55,61.22) v1(51.55,59.32) v1(51.55,57.41) v1(51.65,1.63) v1(51.78,11.31) v1(51.78,6.23) v1(51.86,56.3) v1(52.44,53.47) v1(52.44,50.1) v1(53,30.44) v1(53.05,8.77) v1(53.05,3.69) v1(53.2,54.95) v1(53.36,45.7) v1(53.38,38.92) v1(54.09,54.29) v1(54.32,6.23) v1(54.73,27.67) v1(55.06,54.31) v1(55.08,25.49) v1(55.08,22.95) v1(55.13,50.48) v1(55.46,1.63) v1(55.59,8.77) v1(55.59,3.69) v1(55.82,49.34) v1(56.2,31.23) v1(56.33,25.49) v1(56.33,22.95) v1(56.6,48.47) v1(56.86,6.23) v1(57.18,54.2) v1(57.18,53.44) v1(57.55,49.36) v1(58,54.2) v1(58,53.44) v1(58.13,8.77) v1(58.13,3.69) v1(58.38,50.2) v1(58.46,7.55) v1(58.59,27.69) v1(58.81,54.2) v1(58.81,53.44) v1(59.27,1.63) v1(59.4,6.23) v1(59.5,42.73) v1(59.5,41.26) v1(59.62,54.2) v1(59.62,53.44) v1(60.18,42) v1(60.39,15.99) v1(60.39,14.94) v1(60.34,7.55) v1(60.43,54.2) v1(60.43,53.44) v1(60.67,3.69) v1(60.98,17.99) v1(61.08,6.23) v1(61.25,54.2) v1(61.25,53.44) v1(61.69,18.73) v1(62.06,54.2) v1(62.06,53.44) v1(62.32,13.6) v1(62.32,12.84) v1(62.32,12.08) v1(62.87,54.2) v1(62.87,53.44) v1(63.08,1.63) v1(63.21,3.69) v1(63.39,13.6) v1(63.39,12.84) v1(63.39,12.08) v1(63.69,54.2) v1(63.69,53.44) v1(64,21.17) v1(64,18.86) v1(64.46,13.6) v1(64.46,12.84) v1(64.46,12.08) v1(64.58,49.16) v1(65.19,48.8) v1(65.39,37.52) v1(65.75,3.69) v1(65.9,48.8) v1(66,54.31) v1(66,53.6) v1(66,52.89) v1(66.03,10.68) v1(66.03,9.97) v1(66.49,9.13) v1(66.49,5.95) v1(66.61,48.8) v1(66.66,40.06) v1(66.66,34.98) v1(66.89,1.63) v1(67.2,9.13) v1(67.2,5.95) v1(67.33,48.8) v1(67.93,37.52) v1(67.93,32.44) v1(68.19,8.32) v1(68.19,7.56) v1(68.19,6.79) v1(68.29,3.69) v1(69.2,34.98) v1(69.56,6.23) v1(69.81,21.07) v1(69.81,18.83) v1(69.81,16.14) v1(69.81,13.72) v1(70.47,37.52) v1(70.47,32.44) v1(70.73,10.12) v1(70.7,1.63) v1(70.83,8.77) v1(70.83,3.69) v1(71.74,40.06) v1(71.74,34.98) v1(71.74,29.9) v1(72.1,6.23) v1(72.63,24.82) v1(72.63,10.12) v1(73.01,37.52) v1(73.01,32.44) v1(73.01,27.36) v1(73.37,8.77) v1(73.37,3.69) v1(74.28,40.06) v1(74.28,34.98) v1(74.28,29.9) v1(74.51,1.63) v1(74.54,24.82) v1(74.54,10.12) v1(74.72,9.25) v1(74.72,8.39) v1(74.72,7.53) v1(74.72,6.66) v1(75.55,42.6) v1(75.55,37.52) v1(75.55,32.44) v1(75.55,27.36) v1(75.58,9.25) v1(75.58,8.39) v1(75.58,7.53) v1(75.58,6.66) v1(75.73,50.56) v1(76.49,50.56) v1(76.44,24.82) v1(76.44,10.12) v1(76.44,6.66) v1(76.44,4.76) v1(76.44,2.85) v1(76.88,43.54) v1(76.88,41.64) v1(76.88,39.73) v1(76.88,37.83) v1(76.88,35.92) v1(76.88,34.02) v1(76.88,32.11) v1(76.88,30.21) v1(76.88,28.3) v1(76.88,26.4)
AVDD_H: length 6.2
  TOP w0.279: 64.44,87.6 64.66,87.83 64.39,88.1 U8.17 U8.16 64.44,87.6
  TOP w0.457: E1.2 C56.1 C54.2 64.66,87.83
AVDD_L: length 3.3
  TOP w0.254: U8.22 62.7,91.22
  TOP w0.457: 62.7,91.22 C55.2 C57.1 62.7,93.22 E2.2
AVSS: length 4.3
  TOP w0.254: U2.27 27.37,39.74 26.74,40.36 C20.2
DGND: length 258.1
  TOP w0.152: v2(21.22,87.13) 21.22,87.16
  TOP w0.254: U10.C1 v2(16.35,89.21) ; U9.E5 v2(9.82,87.14) ; U10.E5 21.22,87.16 ; v2(6.85,91.12) 6.85,91.11 U9.B3 ; U9.C1 4.8,89.09 v1(4.69,89.09) ; U10.B3 18.39,90.99 v2(18.28,90.99)
  TOP w0.279: U16.PAD 69.03,74.83 U16.2 70.33,74.83 70.78,74.38 70.81,74.38
  TOP w0.457: D19.2 77.5,83.47 ; D19.2 76.95,82.73 ; D19.2 78.05,82.73 ; D19.2 77.5,82 ; 28.43,89.47 C68.1 27.85,88.94 ; 68.81,72.49 C139.2 68.81,73.63 ; 42.38,104.58 C78.2 43.53,104.58 ; 18.1,100.03 U11.4 19.2,99.43 ; 55.3,87.03 C59.2 ; v1(67.05,80.01) 66.9,80.16 Y1.2 67.66,81.21 ; 4.94,79.57 TP14.1 ; TP14.1 4.94,81.43 ; TP14.1 4.02,80.5 ; TP14.1 5.87,80.5 ; 61.36,93.01 C60.1 ; 46.83,104.58 C77.2 46.25,105.11 ; 62.68,78.04 C126.2 62.15,77.47 ; 64.68,82.36 Y1.4 65.45,83.41 v1(65.3,83.56) ; 2.25,76.83 C146.2 1.68,76.3 ; C92.2 v1(1.91,86.96) ; 28.13,102.4 C96.2 ; D5.2 78.05,89.72 ; D5.2 77.5,90.46 ; D5.2 76.95,89.72 ; D5.2 77.5,88.98 ; 42.33,104.58 C76.2 41.75,105.11 ; C75.2 27.05,92.94 ; 102.17,55.44 TP4.1 ; TP4.1 103.1,56.37 ; TP4.1 101.25,56.37 ; TP4.1 102.17,57.3 ; 53.13,100.73 R46.2 53.66,101.31 ; C67.1 34.03,104.58 ; 49.81,76.58 C107.2 50.35,76.01 ; TP12.1 59.11,76.46 ; TP12.1 57.25,76.46 ; TP12.1 58.18,77.39 ; TP12.1 58.18,75.54 ; 37.94,79.14 C80.2 37.94,78 ; C84.1 v1(13.32,85.88) ; C94.1 v1(12.77,86.42) ; 39.45,105.11 C66.1 40.03,104.58 ; 54.25,104.28 R44.2 ; 48.03,104.58 C79.2 46.88,104.58 ; 57.8,62.16 C121.1 57.23,62.69 ; 75.79,96.69 Q21.2 75.79,95.09 ; C91.2 v1(1.91,88.04) ; 83.31,26.94 TP6.1 ; TP6.1 84.24,27.87 ; TP6.1 85.17,26.94 ; TP6.1 84.24,26.01 ; 66.57,102.25 P1.9 67.23,100.56 ; 6.7,76.33 C102.2 7.24,75.76 ; 44.88,104.58 C73.2 ; 41.81,76.5 C108.1 41.81,75.36 ; 64.54,66.94 JP1.3 ; JP1.3 65.6,67.54 ; JP1.3 66.65,66.94 ; 31.14,76.5 C109.1 31.14,75.36 ; C69.1 54.88,90.69 ; TP16.1 52.44,104.85 ; TP16.1 53.37,103.92 ; TP16.1 52.44,102.99 ; TP16.1 51.51,103.92 ; R62.1 69.4,78.42 ; 56.24,63.98 Q13.2 ; Q13.2 57.23,63.18 ; Q13.2 57.23,64.78 ; 75.79,100.17 Q20.2 75.79,101.77 ; 43.72,77.4 C83.2 ; 71.04,100.56 P1.3 ; 28.43,92.41 C70.2 27.85,92.94 ; C86.2 v1(13.32,86.96) ; R59.2 71.24,77.93 ; 67.62,89.63 C53.2 ; 6.67,73.75 U18.5 6.06,72.54 ; 9.2,101.86 C97.2 8.63,102.39 ; 54.08,83.76 C142.2 54.08,82.61 ; 15.2,75.76 C103.2 14.66,76.33 ; C87.2 v1(24.19,84.26) ; C85.2 v1(13.32,88.04) ; 40.38,104.58 C72.2 ; 72.65,94.69 R126.2 ; v1(24.19,85.34) C88.1 ; 64.34,75.26 C127.2 ; 32.08,104.58 C63.1 ; C65.1 54.88,89.89 ; 43.72,78.2 C82.2 ; 35.05,78.08 C81.2 ; C61.1 55.3,88.97 ; 71.41,104.19 C101.2 70.87,104.76 ; C71.2 54.88,91.69 ; 38.08,104.58 C62.1 ; 69.77,100.56 P1.5 ; 66.35,79.44 C50.2 ; C89.1 v1(24.19,86.42) ; C99.2 62.98,100.79 ; 84.97,14.99 T2.9 ; 63.6,91.08 C55.1 ; C95.1 v1(12.77,85.34) ; C100.2 61.92,100.79 ; 63.81,76.66 R61.2 ; C90.1 v1(1.91,85.88)
  TOP w0.483: S1.2 v1(74.39,93.24) ; S1.2 v1(72.69,93.24) ; S1.2 v1(73.54,91.93) ; S1.2 v1(73.54,94.54) ; C54.1 C56.2 v1(67.52,89.43) ; C54.1 v1(66.72,89.43) ; C54.1 C52.2 v1(65.97,89.46) ; v1(21.95,76.34) U7.11 ; U13.8 v1(23.89,75.12) ; U13.1 v1(32.78,75.12) ; U11.4 v1(20.45,100.03) ; v1(59.76,103.31) 59.47,103.02 C123.2 ; U12.2 v1(42.18,75.12) ; C50.2 v1(67.05,80.01) ; v1(64.3,91.65) C55.1 C57.2 v1(64.3,92.45) ; C74.2 v1(54.34,93.15) ; C74.2 C71.2 v1(54.34,91.19) C69.1 C65.1 v1(54.34,89.15) ; C74.2 55.04,92.49 ; C124.2 v1(60.29,101.13) ; R44.2 v1(54.78,105.39) ; v1(32.65,105.39) C63.1 C67.1 v1(33.45,105.39) ; C60.1 v1(61.93,93.65) ; v1(54.32,88.4) C61.1 C59.2 v1(54.32,87.6) ; C103.2 v1(15.2,77.07) ; C125.2 v1(60.29,104.05) ; P1.3 v1(71.04,104.04) ; v1(47.45,105.39) C79.2 ; v1(44.25,78.78) C82.2 C83.2 v1(44.25,76.66) ; C81.2 35.95,78.65 v1(35.95,78.65) ; R62.1 v1(68.7,77.84) ; C76.2 C72.2 v1(40.95,105.39) ; U7.12 v1(21.3,76.01) ; v1(68.65,90.65) C53.2 v1(67.62,91.83) ; C142.2 54.63,83.19 54.75,83.07 v1(54.85,83.07) ; C64.1 26.3,89.47 ; C64.1 C68.1 ; C64.1 v1(27.05,88.78) ; v1(76.94,100.97) 76.94,100.97 Q20.2 v1(74.63,100.97) ; C51.2 v1(65.3,83.56) ; U12.8 v1(34.56,75.12) ; v1(37.23,78.6) 37.25,78.57 C80.2 ; C127.2 v1(63.64,75.83) ; C66.1 C62.1 v1(38.65,105.39) ; R59.2 v1(72.14,77.33) ; v1(42.95,105.39) C78.2 ; 26.25,92.41 C75.2 C70.2 ; P1.5 v1(69.77,104.1) ; U13.7 v1(25.16,75.11) ; R126.2 v1(73.34,95.27) ; C109.1 v1(31.84,75.93) ; U12.1 v1(43.45,75.12) ; C102.2 v1(7.24,77.07) ; v1(74.63,95.89) Q21.2 v1(76.94,95.89) ; C126.2 v1(62.68,76.7) ; C97.2 v1(7.89,101.86) ; C99.2 v1(62.98,99.64) ; C131.1 71.13,74.18 v1(70.83,74.48) ; v1(13.32,76.03) 13.34,76.02 U6.12 ; C108.1 v1(42.51,75.93) ; C100.2 v1(61.92,99.64) ; v1(71.41,105.39) C101.2 ; P1.9 v1(67.23,104.1) ; C98.1 v1(62.48,102.21) ; C77.2 C73.2 v1(45.45,105.39) ; U12.7 v1(35.83,75.12) ; U13.2 v1(31.51,75.11) ; U6.11 v1(13.99,76.36) ; C96.2 v1(28.87,102.94) ; v1(68.06,73.06) C139.2
  TOP w0.508: C107.2 v1(50.35,77.32) ; v1(19.22,76.33) R37.2 ; U18.5 v1(6.06,75.12) ; C146.2 v1(2.99,76.3)
  TOP w0.762: C115.N 98.24,35.48 ; C115.N 97.17,37.32 ; C115.N 99.31,37.32 ; C115.N 98.24,39.16 ; C134.N 97.84,30.59 ; C134.N 99.83,29.35 ; C134.N 99.83,31.84 ; C134.N 101.83,30.59 ; C140.N 101.83,21.37 ; C140.N 99.83,20.13 ; C140.N 99.83,22.62 ; C140.N 97.84,21.37 ; 91.61,37.32 C133.N ; C133.N 90.54,35.48 ; C133.N 90.54,39.16 ; C133.N 89.47,37.32
  TOP w1.016: T2.9 87.4,14.99 ; T2.9 86.2,15.84 ; T2.9 86.2,14.14
  L2_PWR w0.457: TP4.1 103.1,56.37 ; TP4.1 102.17,57.3 ; TP4.1 101.25,56.37 ; TP4.1 102.17,55.44 ; TP6.1 85.17,26.94 ; TP6.1 84.24,26.01 ; TP6.1 83.31,26.94
  L3_GND w0.457: TP14.1 5.87,80.5 ; TP14.1 4.94,79.57 ; TP14.1 4.94,81.43 ; TP14.1 4.02,80.5 ; 52.44,102.99 TP16.1 ; TP16.1 53.37,103.92 ; TP16.1 51.51,103.92 ; TP16.1 52.44,104.85 ; 102.17,55.44 TP4.1 ; TP4.1 101.25,56.37 ; TP4.1 103.1,56.37 ; TP4.1 102.17,57.3 ; 57.25,76.46 TP12.1 ; TP12.1 58.18,77.39 ; TP12.1 59.11,76.46 ; TP12.1 58.18,75.54 ; 84.24,26.01 TP6.1 ; TP6.1 83.31,26.94 ; TP6.1 85.17,26.94 ; TP6.1 84.24,27.87
  BOTTOM w0.457: TP16.1 53.37,103.92 ; TP16.1 52.44,102.99 ; TP16.1 51.51,103.92 ; TP16.1 52.44,104.85 ; 84.24,26.01 TP6.1 ; TP6.1 85.17,26.94 ; TP6.1 83.31,26.94 ; TP6.1 84.24,27.87 ; TP14.1 4.94,81.43 ; TP14.1 5.87,80.5 ; TP14.1 4.94,79.57 ; TP14.1 4.02,80.5 ; TP12.1 59.11,76.46 ; TP12.1 58.18,77.39 ; TP12.1 58.18,75.54 ; 101.25,56.37 TP4.1 ; TP4.1 102.17,55.44 ; TP4.1 103.1,56.37 ; TP4.1 102.17,57.3
  vias: v1(1.29,104.53) v1(1.29,100.72) v1(1.29,96.91) v1(1.29,93.1) v1(1.29,89.29) v1(1.29,85.48) v1(1.29,81.67) v1(1.29,77.86) v1(1.41,72.4) v1(2.07,105.34) v1(4.69,90.08) v1(5.03,95.55) v1(5.6,96.12) v1(5.55,84.11) v1(5.88,105.39) v1(6.59,92.67) v1(6.79,93.79) v1(7.36,94.36) v1(7.56,72.98) v1(8.37,83.19) v1(9.46,95.41) v1(9.46,72.98) v1(9.69,105.39) v1(10.18,103.51) v1(10.3,92.21) v1(10.3,90.97) v1(11.32,102.6) v1(11.32,101.89) v1(11.37,72.98) v1(11.47,88.83) v1(12.08,93.79) v1(12.08,83.52) v1(12.92,96.27) v1(13.27,72.98) v1(13.4,90.76) v1(13.5,105.39) v1(14.77,103.51) v1(15.15,96.3) v1(15.18,72.98) v1(15.46,89.26) v1(16.27,83.19) v1(16.45,95.55) v1(17.02,96.12) v1(17.08,72.98) v1(17.31,105.39) v1(18.21,93.79) v1(18.78,94.36) v1(19.07,72.98) v1(21.12,105.39) v1(21.05,96.81) v1(21.12,72.98) v1(22.95,94.62) v1(22.95,93.81) v1(23.03,73.01) v1(24.53,72.48) v1(24.93,105.39) v1(25.01,96.5) v1(25.42,92.44) v1(25.44,94.62) v1(25.44,93.81) v1(27.85,88.78) v1(28.34,72.35) v1(28.62,85.12) v1(28.74,105.39) v1(28.74,94.78) v1(28.74,92.39) v1(28.74,88.1) v1(29.28,80.63) v1(31.51,94.78) v1(31.66,98.08) v1(31.77,91.75) v1(32.1,81.52) v1(32.17,89.11) v1(32.15,72.45) v1(32.68,83.19) v1(33.01,91.27) v1(33.24,87.51) v1(33.34,84.46) v1(33.59,89.87) v1(33.7,96.76) v1(33.7,73.01) v1(33.88,86.83) v1(33.87,86.09) v1(33.85,81.54) v1(34.05,83.17) v1(34.15,94.17) v1(35.12,87.89) v1(35.19,72.45) v1(35.45,102.9) v1(35.45,81.59) v1(35.88,83.17) v1(36.36,105.37) v1(36.45,102.9) v1(36.57,86.93) v1(36.57,84.29) v1(38.24,92.66) v1(38.85,89.09) v1(39,72.37) v1(39.46,105.38) v1(39.72,81.47) v1(40.05,83.24) v1(41.77,105.38) v1(42.43,99.12) v1(42.43,91.37) v1(42.81,72.45) v1(43.96,105.39) v1(44.03,92.9) v1(44.47,102.75) v1(45.38,72.65) v1(47.44,91.83) v1(48.94,97.8) v1(48.96,72.65) v1(50,93.3) v1(50.28,95.67) v1(50.31,87.26) v1(50.61,102.09) v1(51.5,105.39) v1(52.77,72.22) v1(53.52,101.96) v1(54.07,70.75) v1(54.07,68.84) v1(54.07,66.94) v1(54.07,65.03) v1(54.07,63.13) v1(54.07,61.22) v1(54.07,59.32) v1(54.85,96.05) v1(55.13,57.31) v1(55.69,102.84) v1(55.68,102.13) v1(55.92,105.39) v1(56.56,62.95) v1(57.36,58.12) v1(57.36,57.35) v1(57.44,62.95) v1(57.9,90.41) v1(58.17,58.12) v1(58.17,57.35) v1(58.99,58.12) v1(58.99,57.35) v1(59.04,67.14) v1(59.5,88.79) v1(59.5,87.82) v1(59.5,86.86) v1(59.5,85.89) v1(59.8,58.12) v1(59.8,57.35) v1(60.31,96.63) v1(60.46,88.79) v1(60.46,87.82) v1(60.46,86.86) v1(60.46,85.89) v1(60.84,59.12) v1(61.12,61.98) v1(61.12,61.22) v1(61.12,58.14) v1(61.12,57.38) v1(61.18,94.19) v1(61.43,88.79) v1(61.43,87.82) v1(61.43,86.86) v1(61.43,85.89) v1(61.68,63.96) v1(61.68,63.2) v1(61.93,58.14) v1(61.93,57.38) v1(62.05,98.75) v1(62.05,97.93) v1(62.05,97.12) v1(62.13,59.92) v1(62.39,88.79) v1(62.39,87.82) v1(62.39,86.86) v1(62.39,85.89) v1(62.49,63.96) v1(62.49,63.2) v1(62.63,75.29) v1(62.81,98.75) v1(62.81,97.93) v1(62.81,97.12) v1(62.75,59.11) v1(62.89,59.92) v1(63.03,105.39) v1(63.08,58.14) v1(63.08,57.38) v1(63.64,76.67) v1(63.89,58.14) v1(63.89,57.38) v1(64.12,79.23) v1(64.38,66.94) v1(65.42,99.42) v1(65.42,96.91) v1(65.79,57.26) v1(66.03,75.09) v1(66.39,102.27) v1(66.82,66.94) v1(66.84,105.39) v1(66.85,77.43) v1(66.92,72.17) v1(67.4,78.57) v1(67.88,76.39) v1(67.88,75.58) v1(67.88,74.77) v1(68.33,70.83) v1(68.33,70.02) v1(68.33,69.21) v1(68.64,76.39) v1(68.64,75.58) v1(68.64,74.77) v1(69.08,94.7) v1(69.1,83.5) v1(69.33,105.39) v1(70.37,80.96) v1(70.95,70.5) v1(70.95,69.69) v1(70.95,68.88) v1(71.64,83.5) v1(71.64,78.42) v1(72.18,88.25) v1(72.91,80.96) v1(74.18,78.42) v1(74.18,70.5) v1(74.18,69.69) v1(74.18,68.88) v1(74.46,105.39) v1(75.45,80.96) v1(75.45,75.88) v1(76.72,78.42) v1(76.79,89.72) v1(76.79,82.74) v1(76.95,93.4) v1(76.95,91.22) v1(77.13,71.15) v1(77.21,67.98) v1(77.49,90.62) v1(77.49,88.82) v1(77.49,83.63) v1(77.51,81.83) v1(77.99,80.96) v1(77.99,75.88) v1(78.21,89.7) v1(78.21,82.74) v1(78.3,61.63) v1(78.3,59.72) v1(78.25,58) v1(78.81,105.22) v1(78.81,103.34) v1(78.81,100.42) v1(78.81,97.93) v1(78.81,95.51) v1(78.81,93.99) v1(79.16,60.71) v1(79.16,58.81) v1(79.16,56.9) v1(79.16,55) v1(79.16,53.09) v1(79.16,51.19) v1(79.16,49.28) v1(79.16,47.38) v1(79.16,45.47) v1(79.16,43.57) v1(79.16,41.66) v1(79.16,39.76) v1(79.16,37.85) v1(79.16,35.95) v1(79.16,34.04) v1(79.16,32.14) v1(79.16,30.23) v1(79.16,28.33) v1(79.16,26.42) v1(79.26,78.42) v1(79.59,24.82) v1(79.59,10.12) v1(79.59,6.64) v1(79.59,4.73) v1(79.59,2.83) v1(80.23,69.63) v1(80.23,66.48) v1(80.46,9.23) v1(80.46,8.37) v1(80.46,7.5) v1(80.46,6.64) v1(80.53,80.96) v1(80.53,75.88) v1(80.53,41.28) v1(80.53,36.2) v1(80.53,31.12) v1(80.53,26.04) v1(80.73,90.69) v1(80.77,92.37) v1(80.77,91.56) v1(81.32,9.23) v1(81.32,8.37) v1(81.32,7.5) v1(81.32,6.64) v1(81.5,24.82) v1(81.5,10.12) v1(81.52,1.61) v1(81.53,92.37) v1(81.53,91.56) v1(81.54,90.69) v1(81.8,78.42) v1(81.8,73.34) v1(81.8,38.74) v1(81.8,33.66) v1(81.8,28.58) v1(81.73,4.36) v1(82.35,90.69) v1(83,6.9) v1(83.07,80.96) v1(83.07,75.88) v1(83.07,70.8) v1(83.07,41.28) v1(83.07,36.2) v1(83.07,31.12) v1(83.07,26.04) v1(83.17,90.69) v1(83.3,68) v1(83.3,65.03) v1(83.3,62.34) v1(83.4,24.82) v1(83.4,10.12) v1(83.98,90.69) v1(84.09,89.67) v1(84.27,4.36) v1(84.34,88.1) v1(84.34,78.42) v1(84.34,73.34) v1(84.34,38.74) v1(84.34,33.66) v1(84.34,28.58) v1(84.79,90.69) v1(85.31,24.82) v1(85.31,10.12) v1(85.33,1.61) v1(85.61,80.96) v1(85.61,75.88) v1(85.61,70.8) v1(85.56,16.26) v1(85.56,13.7) v1(85.54,6.9) v1(85.71,89.67) v1(85.71,60.56) v1(86.81,9.44) v1(86.81,4.36) v1(86.88,88.1) v1(86.83,16.26) v1(86.83,13.7) v1(87.32,89.67) v1(88.03,63.28) v1(88.03,62.47) v1(87.98,15.5) v1(87.98,14.49) v1(88.08,6.9) v1(88.99,60.74) v1(89.09,37.92) v1(89.09,36.7) v1(89.14,1.61) v1(89.35,14.52) v1(89.35,9.44) v1(89.35,4.36) v1(89.73,59.24) v1(89.73,58.45) v1(89.83,49.36) v1(89.93,61.45) v1(89.98,39.52) v1(89.96,35.13) v1(90.61,57.3) v1(90.61,56.54) v1(90.62,11.98) v1(90.62,6.9) v1(90.64,52.59) v1(91.13,39.52) v1(91.13,35.13) v1(91.3,49.84) v1(91.42,57.3) v1(91.42,56.54) v1(91.89,14.52) v1(91.89,9.44) v1(91.89,4.36) v1(91.99,37.92) v1(91.99,36.7) v1(92.24,57.3) v1(92.24,56.54) v1(92.95,1.61) v1(93.05,57.3) v1(93.05,56.54) v1(93.16,17.06) v1(93.16,11.98) v1(93.16,6.9) v1(93.31,39.86) v1(93.31,37.32) v1(93.31,34.78) v1(93.89,49.82) v1(94.43,14.52) v1(94.43,9.44) v1(94.43,4.36) v1(95.57,39.86) v1(95.57,37.32) v1(95.57,34.78) v1(95.7,17.06) v1(95.7,11.98) v1(95.7,6.9) v1(96.03,87.89) v1(96.03,82.81) v1(96.79,37.92) v1(96.79,36.7) v1(96.76,1.61) v1(96.9,33.55) v1(96.97,24.68) v1(96.97,19.6) v1(96.97,14.52) v1(96.97,9.44) v1(96.97,4.36) v1(97.3,85.35) v1(97.3,80.27) v1(97.58,62.39) v1(97.58,60.59) v1(97.63,31.17) v1(97.63,30.03) v1(97.63,21.95) v1(97.63,20.81) v1(97.68,39.52) v1(97.66,35.13) v1(98.04,89.59) v1(98.24,27.22) v1(98.24,17.06) v1(98.24,11.98) v1(98.24,6.9) v1(98.57,87.89) v1(98.57,82.81) v1(98.57,77.73) v1(98.82,39.52) v1(98.82,35.13) v1(98.87,61.48) v1(99.23,32.04) v1(99.23,29.14) v1(99.23,22.82) v1(99.23,19.92) v1(99.44,33.55) v1(99.51,24.68) v1(99.51,14.52) v1(99.51,9.44) v1(99.51,4.36) v1(99.63,58.96) v1(99.69,37.92) v1(99.69,36.7) v1(99.84,85.35) v1(99.84,80.27) v1(100.45,32.04) v1(100.45,29.14) v1(100.45,22.82) v1(100.45,19.92) v1(100.57,1.61) v1(100.78,37.38) v1(100.78,27.22) v1(100.78,17.06) v1(100.78,11.98) v1(100.78,6.9) v1(101.11,87.89) v1(101.11,82.81) v1(101.11,77.73) v1(101.11,47.58) v1(101.85,89.59) v1(101.87,44.97) v1(101.87,42.43) v1(101.87,39.89) v1(101.98,33.55) v1(102.02,31.17) v1(102.02,30.01) v1(102.02,21.95) v1(102.02,20.79) v1(102.05,24.68) v1(102.05,19.6) v1(102.05,14.52) v1(102.05,9.44) v1(102.05,4.36) v1(102.22,53.3) v1(102.22,52.49) v1(102.22,51.67) v1(102.22,49.95) v1(102.22,49.13) v1(102.22,48.32) v1(103.29,88.15) v1(103.29,84.34) v1(103.29,80.53) v1(103.29,76.72) v1(103.29,72.91) v1(103.29,69.1) v1(103.29,65.29) v1(103.29,61.48) v1(103.29,57.67) v1(103.29,53.86) v1(103.29,50.05) v1(103.29,46.24) v1(103.29,42.43) v1(103.29,38.62) v1(103.29,34.81) v1(103.29,31) v1(103.29,27.19) v1(103.29,23.38) v1(103.29,19.57) v1(103.29,15.76) v1(103.29,11.95) v1(103.29,8.14) v1(103.29,4.33) v2(4.84,86.32) v2(5.88,90.08) v2(5.85,88.25) v2(5.87,86.31) v2(6.87,88.25) v2(6.9,86.32) v2(8.8,90.99) v2(8.8,89.09) v2(9.79,88.07) v2(16.26,86.32) v2(17.29,90.1) v2(17.29,86.31) v2(18.28,88.25) v2(18.32,86.32) v2(20.23,90.97) v2(20.23,89.04)
GND_EARTH: length 36.8
  TOP w0.762: 80.8,102.43 TP2.1 ; TP2.1 80.8,100.94 ; TP2.1 82.29,102.43 ; TP2.1 82.29,100.94 ; P3.3 96.31,93.91 ; P3.3 97.55,92.67 ; P3.3 98.8,93.91 ; P3.3 97.55,95.16
  L2_PWR w0.762: 80.8,100.94 TP2.1 ; TP2.1 82.29,102.43 ; TP2.1 80.8,102.43 ; TP2.1 82.29,100.94 ; P3.3 98.8,93.91 ; P3.3 96.31,93.91 ; P3.3 97.55,92.67 ; P3.3 97.55,95.16
  L3_GND w0.762: 96.31,93.91 P3.3 ; P3.3 97.55,95.16 ; P3.3 97.55,92.67 ; P3.3 98.8,93.91 ; TP2.1 82.29,100.94 ; TP2.1 80.8,102.43 ; TP2.1 82.29,102.43 ; TP2.1 80.8,100.94
  BOTTOM w0.762: TP2.1 82.29,100.94 ; TP2.1 80.8,102.43 ; TP2.1 80.8,100.94 ; TP2.1 82.29,102.43 ; P3.3 98.8,93.91 ; P3.3 97.55,95.16 ; P3.3 97.55,92.67 ; P3.3 96.31,93.91
  vias: v1(80.93,104.15) v1(80.93,103.19) v1(80.93,100.29) v1(80.93,99.33) v1(80.93,98.36) v1(81.9,104.15) v1(81.9,103.19) v1(81.9,100.29) v1(81.9,99.33) v1(81.9,98.36) v1(91.37,104.87) v1(91.37,98.59) v1(91.37,97.63) v1(92.34,104.87) v1(92.34,98.59) v1(92.34,97.63) v1(96.59,95.08) v1(96.59,92.54) v1(97.6,104.83) v1(97.6,102.4) v1(97.86,96.35) v1(98.57,104.83) v1(98.57,102.4) v1(99.13,97.62) v1(99.13,96.35) v1(99.13,95.08) v1(99.13,93.81) v1(99.13,92.54) v1(99.53,104.83) v1(99.53,102.4) v1(100.4,97.62) v1(100.4,96.35) v1(100.4,95.08) v1(100.4,93.81) v1(100.4,92.54) v1(101.67,97.62) v1(101.67,96.35) v1(101.67,95.08) v1(101.67,93.81) v1(101.67,92.54) v1(102.94,97.62) v1(102.94,96.35) v1(102.94,95.08) v1(102.94,93.81) v1(102.94,92.54)
V5: length 4.2
  TOP w0.305: U3.31 28.33,61.39 27.72,62.01 C42.2
VCC_1: length 4.1
  TOP w0.254: R64.1 C131.2 70.76,75.08 70.51,75.33 U16.3
VDD_1: length 0.8
  TOP w0.305: U3.17 32.91,55.18
VDD_2: length 0.6
  TOP w0.305: U3.20 32.65,56.68
VDD_3: length 0.8
  TOP w0.305: U3.41 24.27,56.68
VDD_4: length 0.8
  TOP w0.305: U3.44 24.3,55.18
VDD_24V: length 18
  TOP w0.305: 22.85,33.72 C27.2 22.64,33.72 ; 22.85,33.72 22.64,33.72 ; 22.85,33.72 U2.42 ; 22.64,33.72 19.72,33.72 C26.2 ; C18.2 37.28,32.9 36.88,33.3 C19.2 36.7,33.72 U2.7
  L2_PWR w0.889: S2.6 64.82,39.38 ; S2.6 63.39,40.82 ; S2.6 63.39,37.95 ; S2.6 61.95,39.38
  vias: v1(18.46,34.63) v1(18.46,33.71) v1(40.43,33.36) v1(40.43,32.44) v1(72.86,44.56) v1(73.62,46.09) v1(73.62,45.33) v1(73.62,44.56) v1(74.38,46.09) v1(74.38,45.33) v1(74.38,44.56)
VDD_24V_MAX14906: length 8.3
  TOP w0.457: 30.8,50.9 C41.1 ; C41.1 31.33,51.24 31.08,51.49 ; C41.1 31.33,50.33 ; R34.1 v1(13.12,50.94)
  TOP w0.762: S2.5 61.95,34.68 ; S2.5 64.82,34.68 ; S2.5 63.39,33.25 ; S2.5 63.39,36.12
  vias: v1(15.89,58.82) v1(15.89,58.06) v1(15.89,57.3) v1(15.89,54.55) v1(15.89,53.79) v1(15.89,53.03) v1(16.66,58.82) v1(16.66,58.06) v1(16.66,57.3) v1(16.66,54.55) v1(16.66,53.79) v1(16.66,53.03) v1(33.99,48.93) v1(33.99,48.17) v1(34.8,48.93) v1(34.8,48.17) v1(40.46,58.82) v1(40.46,58.06) v1(40.46,57.3) v1(40.46,54.57) v1(40.46,53.81) v1(40.46,53.05) v1(41.22,58.82) v1(41.22,58.06) v1(41.22,57.3) v1(41.22,54.57) v1(41.22,53.81) v1(41.22,53.05) v1(46.32,48.07) v1(46.32,46.8) v1(46.32,45.53) v1(46.95,49.21) v1(47.59,48.07) v1(47.59,46.8) v1(47.59,45.53) v1(48.22,49.21) v1(48.86,48.07) v1(48.86,46.8) v1(48.86,45.53) v1(49.49,49.21) v1(50.13,48.07) v1(50.13,46.8)
VDDOK: length 11
  TOP w0.178: U3.3 26.83,51.91 25.26,50.33 17.88,50.33 DS9.C
VIN_SYS: length 3.3
  TOP w0.457: C139.1 69.71,73.63 ; C139.1 70.24,73.06 ; C139.1 69.71,72.49
  TOP w0.61: 65.6,64.66 JP1.1 64.54,65.26
  vias: v1(65.02,64.2) v1(65.02,63.49) v1(65.73,64.2) v1(65.73,63.49) v1(74.9,72.65) v1(74.9,71.95) v1(75.61,72.65) v1(75.61,71.95) v1(75.89,66.29) v1(75.89,65.58) v1(76.6,66.29) v1(76.6,65.58) v1(77.31,66.29) v1(77.31,65.58) v1(83.41,46.7) v1(83.41,45.99) v1(84.12,46.7) v1(84.12,45.99) v1(87.04,32.37) v1(87.04,31.67) v1(87.75,32.37) v1(87.75,31.67)
AD74413R_ADC_RDY: length 28.9
  TOP w0.178: U1.75 v1(32.95,81.42) ; U6.18 v1(9.44,77.02)
  BOTTOM w0.178: v1(32.95,81.42) 32.83,81.42 31.07,79.65 12.61,79.65 9.98,77.02 v1(9.44,77.02)
AD74413R_ADC_RDY_ISO: length 56.8
  TOP w0.178: v1(9.82,65.13) 9.82,66.09 9.44,66.48 U6.3 ; U2.52 26.37,28.67 v1(25.97,28.28)
  TOP w0.203: R84.2 9.73,65.09 9.77,65.13 v1(9.82,65.13)
  BOTTOM w0.178: v1(9.82,65.13) 11.5,63.46 11.5,62.95 12.66,61.78 18.64,61.78 19.32,61.11 24.19,61.11 26,59.3 26,42.09 26.64,41.46 26.64,40.2 24.91,38.46 24.91,30.21 25.97,29.14 v1(25.97,28.28)
AD74413R_ALERT: length 56.5
  TOP w0.178: v1(58.08,60.87) 58.08,60.29 58.23,60.14 U25.38 ; v1(45.93,95.22) 44.44,96.71 37.38,96.71 34.45,99.63 U1.31
  BOTTOM w0.178: v1(45.93,95.22) 46.85,94.29 46.85,84.67 56.28,75.24 56.28,64.91 58.08,63.1 v1(58.08,60.87)
AD74413R_ALERT_ISO: length 65.9
  TOP w0.203: v1(49.98,28.03) 43.47,21.52 30.04,21.52 26.15,25.41 26.15,27.54 26.84,28.23 26.84,29.92 U2.53 ; v1(63.85,50.83) 63.23,51.45 U25.21 ; R79.2 v1(55,42.86)
  BOTTOM w0.203: v1(63.85,50.83) 61.64,50.83 55.57,44.75 55.57,43.42 v1(55,42.86) 51.6,39.46 51.6,29.65 v1(49.98,28.03)
AD74413R_GPO_A: length 35.1
  TOP w0.178: v1(44.01,91.98) 42.2,93.79 36.21,93.79 33.92,96.07 31.21,96.07 30.82,95.69 U1.45 ; U14.5 v1(48.65,76.36)
  BOTTOM w0.178: v1(44.01,91.98) 44.01,84.79 48.65,80.16 v1(48.65,76.36)
